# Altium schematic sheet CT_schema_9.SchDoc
size 281 x 153 mm
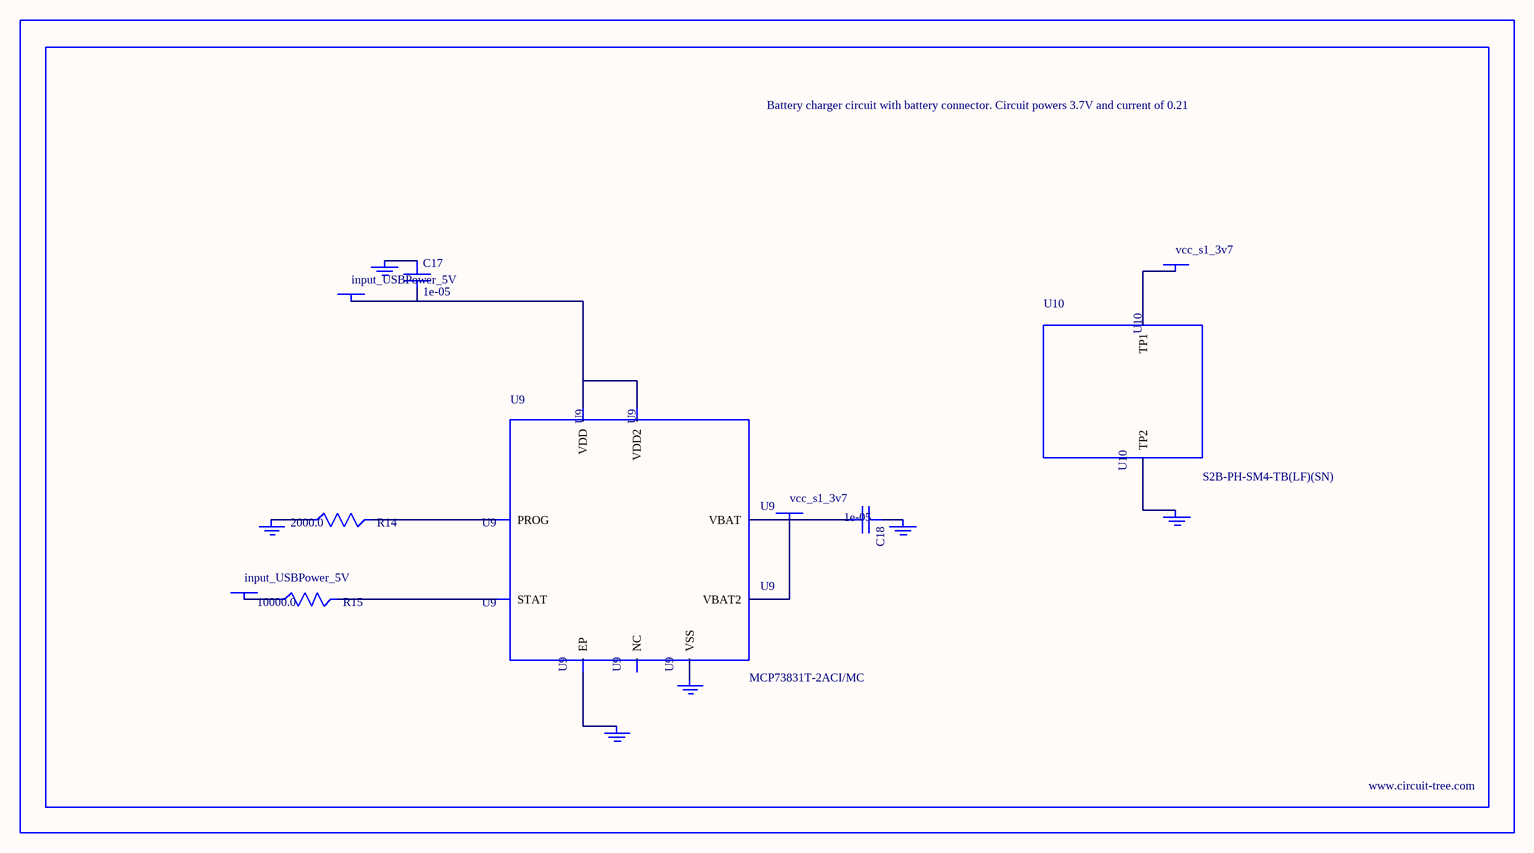
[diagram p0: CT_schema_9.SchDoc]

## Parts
BORDER8  (no value)
C17  1e-05  [C1206]
C18  1e-05  [C1206]
GND_INSTANCE_8_0  (no value)
GND_INSTANCE_8_1  (no value)
GND_INSTANCE_8_2  (no value)
GND_INSTANCE_8_3  (no value)
GND_INSTANCE_8_4  (no value)
GND_INSTANCE_8_5  (no value)
POWER_INSTANCE_8_0  input_USBPower_5V
POWER_INSTANCE_8_1  input_USBPower_5V
POWER_INSTANCE_8_2  vcc_s1_3v7
POWER_INSTANCE_8_3  vcc_s1_3v7
R14  2000.0  [R0603]
R15  10000.0  [R0603]
U9  MCP73831T-2ACI/MC  [DFN8_2X3MC]
U10  S2B-PH-SM4-TB(LF)(SN)  [JST-2-SMD]

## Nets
NetC17_1: C17.1 GND_INSTANCE_8_0.0(GND)
NetC17_2: C17.2 POWER_INSTANCE_8_0.0(PWR) U9.1(VDD) U9.2(VDD2)
NetC18_1: C18.1 GND_INSTANCE_8_1.0(GND)
NetC18_2: C18.2 POWER_INSTANCE_8_2.0(PWR) U9.3(VBAT) U9.4(VBAT2)
NetGND_INSTANCE_8_2_0: GND_INSTANCE_8_2.0(GND) R14.1
NetGND_INSTANCE_8_3_0: GND_INSTANCE_8_3.0(GND) U9.9(EP)
NetGND_INSTANCE_8_4_0: GND_INSTANCE_8_4.0(GND) U9.6(VSS)
NetGND_INSTANCE_8_5_0: GND_INSTANCE_8_5.0(GND) U10.2(TP2)
NetPOWER_INSTANCE_8_1_0: POWER_INSTANCE_8_1.0(PWR) R15.1
NetPOWER_INSTANCE_8_3_0: POWER_INSTANCE_8_3.0(PWR) U10.1(TP1)
NetR14_2: R14.2 U9.8(PROG)
NetR15_2: R15.2 U9.5(STAT)

Not connected (* = marked no-connect by the designer): U9 7(NC)

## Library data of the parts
BORDER8 = BORDER_PAGE8
C17 C18 = C1206C106K3RACTU
GND_INSTANCE_8_0-GND_INSTANCE_8_5 = GND
POWER_INSTANCE_8_0-POWER_INSTANCE_8_3 = PWR
R14 = RC0603JR-072KL
R15 = RC0603JR-0710KL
